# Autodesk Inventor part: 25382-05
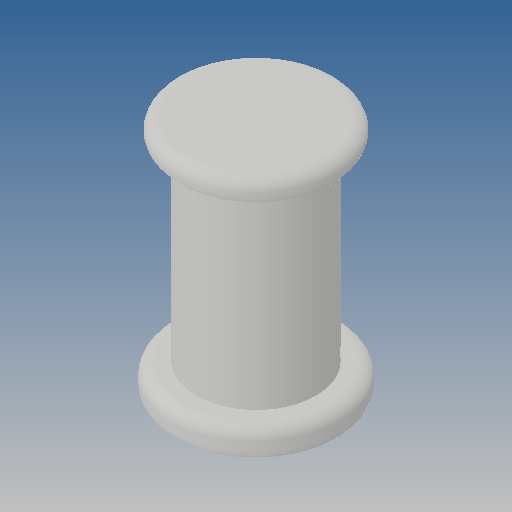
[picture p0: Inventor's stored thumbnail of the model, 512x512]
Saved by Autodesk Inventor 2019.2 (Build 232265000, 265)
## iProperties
Created: 2012-09
Part Number: 25382-05
Material: Ogólny
Document SubType Name: Modeling
Designer: CADENGINEERING4
Density: 1 g/cm^3
Appearance: Domyślna
Author: CADENGINEERING4
Revision Number: ÈÎºÎ
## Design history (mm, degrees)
feature "Ðý×ª1"
node "Bryła1"
